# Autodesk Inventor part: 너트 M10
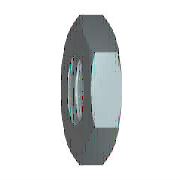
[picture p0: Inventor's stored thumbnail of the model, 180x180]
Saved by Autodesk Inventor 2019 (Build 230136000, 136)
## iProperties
IsCustomPart: 1
Created: 2012-02
Part Number: 너트 M10
Material: 스테인리스강
Description: 미터법 정밀 피치 스레드가 있는 6각 가는 너트(모따기됨)
Document SubType Name: Modeling
Standard: ISO 8675
Designer: mduedu
Standard Revision: Second edition 1999-08-15
Standards Organization: ISO
Language: ko-KR
Size Designation: M10 x 1
Categories: <MemberInstance><Categories><Category DisplayName="조임쇠" InternalName="e4da775c-781d-43d5-af7c-5136215cf5a6" Mnemonic="FSTN"><Category DisplayName="너트" InternalN
Density: 8.08 g/cm^3
Appearance: 기본값
Author: mduedu
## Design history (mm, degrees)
sketch "스케치1"
  geometry: L1 (-9.238, 0)-(-4.619, 8); L2 (-4.619, 8)-(4.619, 8); L3 (4.619, 8)-(9.238, 0); L4 (9.238, 0)-(4.619, -8); L5 (4.619, -8)-(-4.619, -8); L6 (-4.619, -8)-(-9.238, 0); 2 further points
  constraints: 12 end point, 1 coincident, 1 horizontal, 11 other
  dimensions: "d0" = 18.47521 distance of L3.end L1.start (= 1.1547 x SW)
extrude "본체" new body sketch "스케치1" distance "d1" = 5 (= KOH); taper "d2" = 0 deg
sketch "스케치2"
  geometry: L1 (0, 4.619)-(0, 9.238) reference; L2 (0, 9.238)-(5, 9.238) reference; L3 (5, 4.619)-(5, 9.238) reference; L4 (-1, 0)-(6, 0) reference; L5 (1.11, 9.238)-(0, 7.315); L6 (3.89, 9.238)-(5, 7.315)
  constraints: 4 end point, 4 point on line
  dimensions: "d3" = 30 deg angle of L1 L5 (= ANG1); "d4" = 30 deg angle of L3 L6 (= ANG2); "d5" = 14.63 diameter of L5.end L4 (= SW0); "d6" = 14.63 diameter of L6.end L4 (= SW01)
revolve "모따기1" sketch "스케치2" stored, may be unused: angle "d7" = 90 deg
sketch "스케치3"
  geometry: 4 further points
  constraints: 1 coincident, 1 other
hole "스레드" sketch "스케치3" at (0, 0) diameter "d25" = 8.91747; stored, may be unused: countersink angle "d29" = 82 deg, drill point angle "d31" = 118 deg; dims "d26" = 6, "d27" = 4, "d28" = 2, "d30" = 8
workaxis "Work Axis1"
workplane "Work Plane1"
body "Solid1"
chamfer "모따기2" distance "d8" = 0.54127 (= -0.5 x GD1 + 0.5 x NND); stored, may be unused: angle "d9" = 30 deg, second distance "d40" = 0.54127 (= -0.5 x GD1 + 0.5 x NND)
chamfer "모따기3" distance "d10" = 0.54127 (= -0.5 x GD1 + 0.5 x NND); stored, may be unused: angle "d11" = 30 deg, second distance "d41" = 0.54127 (= -0.5 x GD1 + 0.5 x NND)
other parameters: "ANG1" = 30 deg [user parameter; used in 1 equation term], "ANG2" = 30 deg [user parameter; used in 1 equation term], "KOH" = 5 [user parameter; used in 1 equation term], "SW" = 16 [user parameter; used in 1 equation term], "SW0" = 14.63 [user parameter; used in 2 equation terms], "SW01" = 14.63 (= SW0) [user parameter; used in 1 equation term], "GD1" = 8.91747 (computed from THREADDIA, PTC, TOA) [user parameter; used in 4 equation terms], "d13" = 0, "d14" = 0, "d39" = 0, "d42" = 0, "GUL" = 0.54127 (= 0.541266 x PTC) [user parameter], "TOA" = 30 deg [user parameter; used in 1 equation term], "PTC" = 1 [user parameter; used in 4 equation terms], "E0" = 17.77 [user parameter], "GAL" = 0.54127 (= 0.541266 x PTC) [user parameter]
